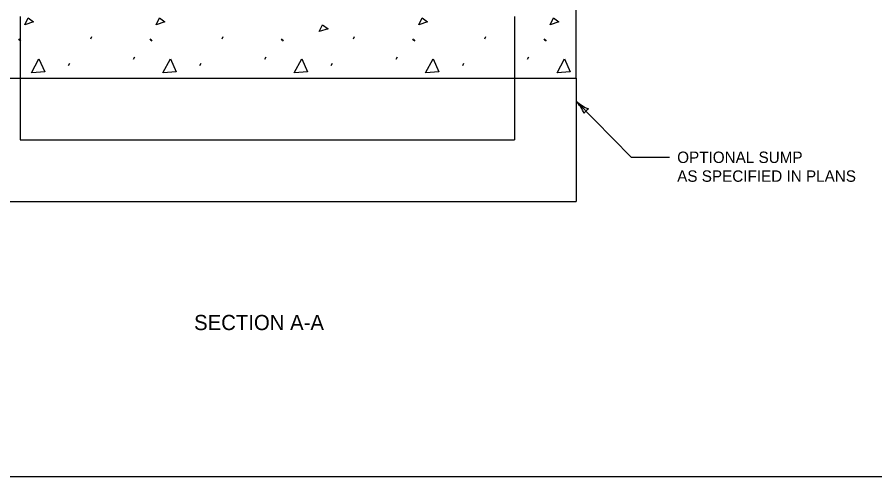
# Model space of a CAD drawing. Extents: x 49991.4 to 50057, y 49987.6 to 50011.4.
# Drawn here: x 50001.401 to 50005.915, y 49987.799 to 49990.219 of the extents above; entities that cross this region are included whole.
import ezdxf

# ---------------------------------------------------------------- set-up
doc = ezdxf.new("R2010")
doc.units = 0
for name, color, linetype in [('Level 1', 7, 'Continuous'), ('Level 2', 7, 'Continuous'), ('Level 3', 7, 'Continuous'), ('Level 4', 7, 'Continuous')]:
    doc.layers.add(name, color=color, linetype=linetype)

msp = doc.modelspace()

# ---------------------------------------------------------------- linework, layer by layer
at = {"layer": 'Level 1'}
for p, q in [((50004.3429, 49989.8979), (50004.3429, 49991.8479)), ((50001.4079, 49990.1044), (50001.4137, 49990.0957)), ((50001.4137, 49990.1011), (50001.4194, 49990.0924)), ((50001.7889, 49990.1044), (50001.7946, 49990.1174)), ((50002.0991, 49990.1044), (50002.1049, 49990.0957)), ((50002.1049, 49990.1011), (50002.1107, 49990.0924)), ((50002.4801, 49990.1044), (50002.4859, 49990.1174)), ((50002.7903, 49990.1044), (50002.7961, 49990.0957)), ((50002.7961, 49990.1011), (50002.8019, 49990.0924)), ((50003.1713, 49990.1044), (50003.1771, 49990.1174)), ((50003.4816, 49990.1044), (50003.4874, 49990.0957)), ((50003.4874, 49990.1011), (50003.4931, 49990.0924)), ((50003.8626, 49990.1044), (50003.8683, 49990.1174)), ((50004.1728, 49990.1044), (50004.1786, 49990.0957)), ((50004.1786, 49990.1011), (50004.1844, 49990.0924)), ((50002.014, 49989.9974), (50002.0197, 49990.0104)), ((50002.7052, 49989.9974), (50002.711, 49990.0104)), ((50003.3964, 49989.9974), (50003.4022, 49990.0104)), ((50004.0877, 49989.9974), (50004.0934, 49990.0104)), ((50001.672, 49989.9642), (50001.6777, 49989.9772)), ((50002.3632, 49989.9642), (50002.369, 49989.9772)), ((50003.0544, 49989.9642), (50003.0602, 49989.9772)), ((50003.7457, 49989.9642), (50003.7514, 49989.9772)), ((50001.0929, 49989.8979), (50004.3429, 49989.8979))]:
    msp.add_line(p, q, dxfattribs=at)
msp.add_lwpolyline([(49999.3835, 49998.9992), (50016.7501, 49998.9992), (50016.7501, 49987.7988), (49999.3835, 49987.7988)], close=True, dxfattribs=at)
for points in [[(50001.4411, 49990.1794), (50001.4584, 49990.2155), (50001.4873, 49990.1939), (50001.4411, 49990.1794)], [(50002.1323, 49990.1794), (50002.1496, 49990.2155), (50002.1785, 49990.1939), (50002.1323, 49990.1794)], [(50003.5148, 49990.1794), (50003.5321, 49990.2155), (50003.561, 49990.1939), (50003.5148, 49990.1794)], [(50004.206, 49990.1794), (50004.2233, 49990.2155), (50004.2522, 49990.1939), (50004.206, 49990.1794)], [(50002.991, 49990.1426), (50003.0084, 49990.1786), (50003.0372, 49990.157), (50002.991, 49990.1426)], [(50001.4772, 49989.9253), (50001.5161, 49989.9989), (50001.5464, 49989.9311), (50001.4786, 49989.9253)], [(50002.1684, 49989.9253), (50002.2074, 49989.9989), (50002.2377, 49989.9311), (50002.1698, 49989.9253)], [(50002.8596, 49989.9253), (50002.8986, 49989.9989), (50002.9289, 49989.9311), (50002.8611, 49989.9253)], [(50003.5509, 49989.9253), (50003.5898, 49989.9989), (50003.6201, 49989.9311), (50003.5523, 49989.9253)], [(50004.2421, 49989.9253), (50004.2811, 49989.9989), (50004.3114, 49989.9311), (50004.2435, 49989.9253)]]:
    msp.add_lwpolyline(points, dxfattribs=at)
at = {"layer": 'Level 3'}
for p, q in [((50004.3429, 49989.7774), (50004.6326, 49989.4812)), ((50004.6326, 49989.4812), (50004.8345, 49989.4812))]:
    msp.add_line(p, q, dxfattribs=at)
for centre, radius, start, end in [((50004.1796, 49989.6265), 0.2223, 22.5571, 42.7406), ((50004.499, 49989.9504), 0.233, 227.9284, 247.1783), ((50004.4337, 49989.6869), 0.0548, 117.2399, 152.9623)]:
    msp.add_arc(centre, radius, start, end, dxfattribs=at)
at = {"layer": 'Level 4'}
for p, q in [((50001.4179, 49990.2229), (50001.4179, 49989.5729)), ((50004.0179, 49990.2229), (50004.0179, 49989.5729)), ((50004.3429, 49989.8979), (50004.3429, 49989.2479)), ((50001.4179, 49989.5729), (50004.0179, 49989.5729)), ((50001.0929, 49989.2479), (50004.3429, 49989.2479))]:
    msp.add_line(p, q, dxfattribs=at)

# ---------------------------------------------------------------- texts
at = {"layer": 'Level 2'}
for s, height, p in [('OPTIONAL SUMP ', 0.06, (50004.8745, 49989.4512)), ('AS SPECIFIED IN PLANS', 0.06, (50004.8745, 49989.3522)), ('SECTION A-A', 0.08, (50002.3323, 49988.5714))]:
    msp.add_text(s, height=height, dxfattribs=at).set_placement(p)

doc.saveas('drawing.dxf')
